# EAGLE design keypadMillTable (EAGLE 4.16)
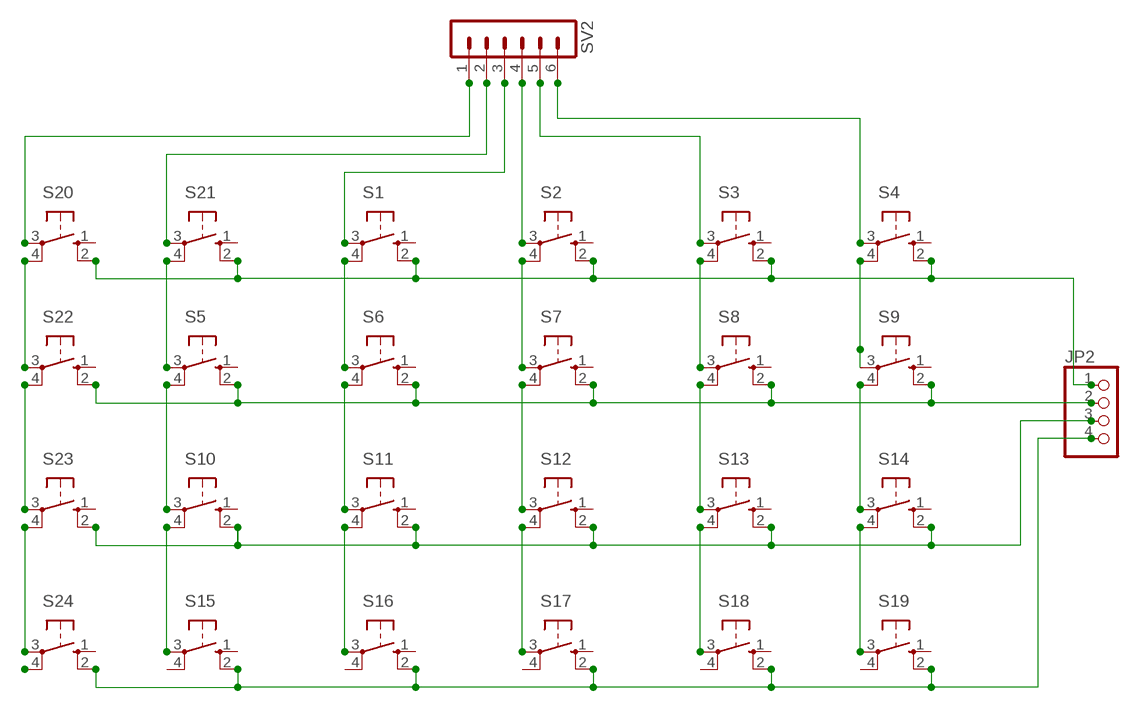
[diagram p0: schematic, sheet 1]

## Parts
JP2  PINHD-1X4  [1X04]
S1  10-XX  [B3F-10XX]
S2  10-XX  [B3F-10XX]
S3  10-XX  [B3F-10XX]
S4  10-XX  [B3F-10XX]
S5  10-XX  [B3F-10XX]
S6  10-XX  [B3F-10XX]
S7  10-XX  [B3F-10XX]
S8  10-XX  [B3F-10XX]
S9  10-XX  [B3F-10XX]
S10  10-XX  [B3F-10XX]
S11  10-XX  [B3F-10XX]
S12  10-XX  [B3F-10XX]
S13  10-XX  [B3F-10XX]
S14  10-XX  [B3F-10XX]
S15  10-XX  [B3F-10XX]
S16  10-XX  [B3F-10XX]
S17  10-XX  [B3F-10XX]
S18  10-XX  [B3F-10XX]
S19  10-XX  [B3F-10XX]
S20  10-XX  [B3F-10XX]
S21  10-XX  [B3F-10XX]
S22  10-XX  [B3F-10XX]
S23  10-XX  [B3F-10XX]
S24  10-XX  [B3F-10XX]
SV2  MA06-1  [MA06-1]

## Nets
N$1: S21.3(P) SV2.2
N$2: S10.4(P1) S15.3(P)
N$3: S4.3(P) SV2.6
N$4: S5.3(P) S21.4(P1)
N$5: S5.4(P1) S10.3(P)
N$7: S1.3(P) SV2.3
N$8: S1.4(P1) S6.3(P)
N$9: S6.4(P1) S11.3(P)
N$10: S2.3(P) SV2.4
N$11: S2.4(P1) S7.3(P)
N$12: S7.4(P1) S12.3(P)
N$13: S3.3(P) SV2.5
N$14: S3.4(P1) S8.3(P)
N$15: S8.4(P1) S13.3(P)
N$16: S14.4(P1) S19.3(P)
N$17: S9.4(P1) S14.3(P)
N$18: S4.4(P1) S9.3(P)
N$21: S11.4(P1) S16.3(P)
N$26: JP2.4 S15.2(S1) S16.2(S1) S17.2(S1) S18.2(S1) S19.2(S1) S24.2(S1)
N$28: S20.4(P1) S22.3(P)
N$29: JP2.1 S1.2(S1) S2.2(S1) S3.2(S1) S4.2(S1) S20.2(S1) S21.2(S1)
N$30: S22.4(P1) S23.3(P)
N$32: S23.4(P1) S24.3(P)
N$34: S24.4(P1)
N$35: S20.3(P) SV2.1
N$37: S12.4(P1) S17.3(P)
N$40: JP2.2 S5.2(S1) S6.2(S1) S7.2(S1) S8.2(S1) S9.2(S1) S22.2(S1)
N$46: JP2.3 S10.2(S1) S11.2(S1) S12.2(S1) S13.2(S1) S14.2(S1) S23.2(S1)
N$60: S13.4(P1) S18.3(P)
Unconnected: S1.1(S) S2.1(S) S3.1(S) S4.1(S) S5.1(S) S6.1(S) S7.1(S) S8.1(S) S9.1(S) S10.1(S) S11.1(S) S12.1(S) S13.1(S) S14.1(S) S15.1(S) S15.4(P1) S16.1(S) S16.4(P1) S17.1(S) S17.4(P1) S18.1(S) S18.4(P1) S19.1(S) S19.4(P1) S20.1(S) S21.1(S) S22.1(S) S23.1(S) S24.1(S)

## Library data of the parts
JP2 = pinhead:PINHD-1X4: PIN HEADER
S1-S24 = switch-omron:10-XX: OMRON SWITCH
SV2 = con-lstb:MA06-1: PIN HEADER

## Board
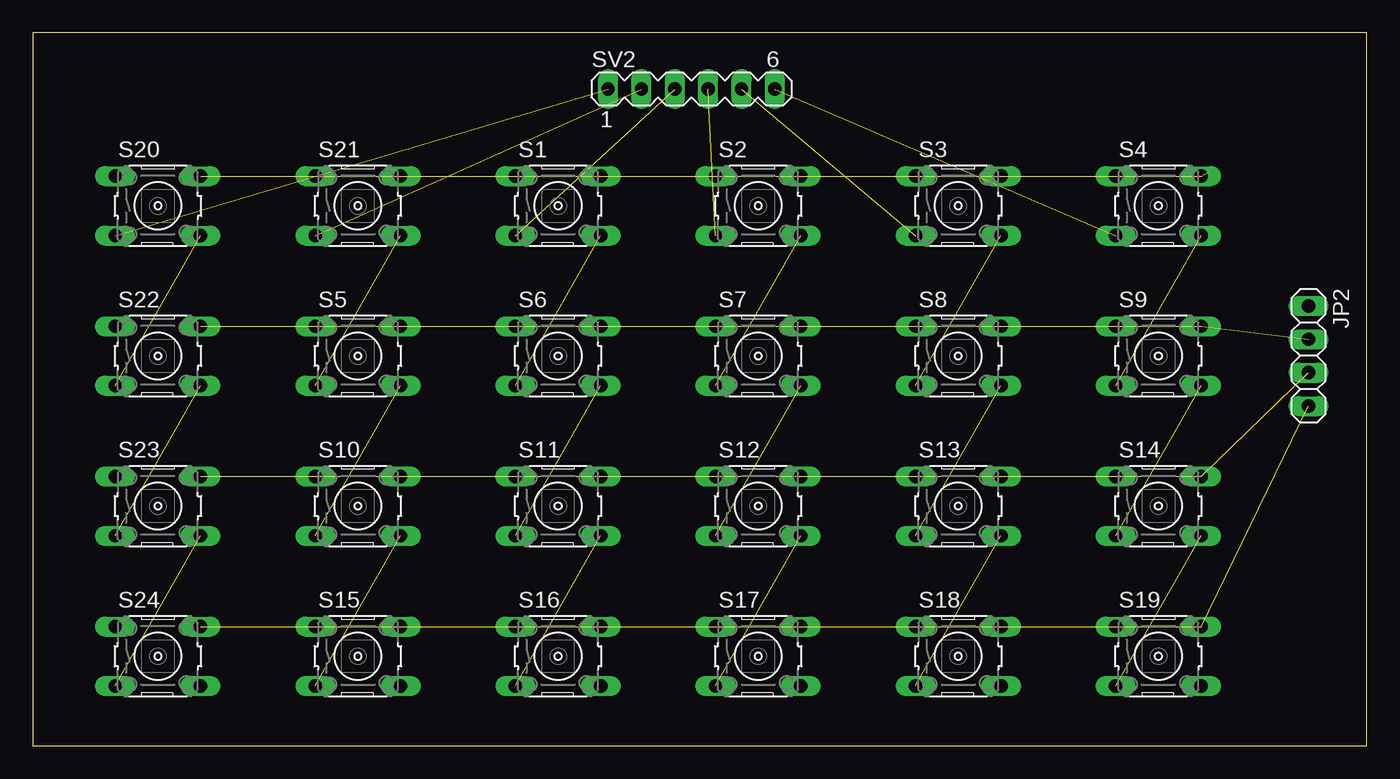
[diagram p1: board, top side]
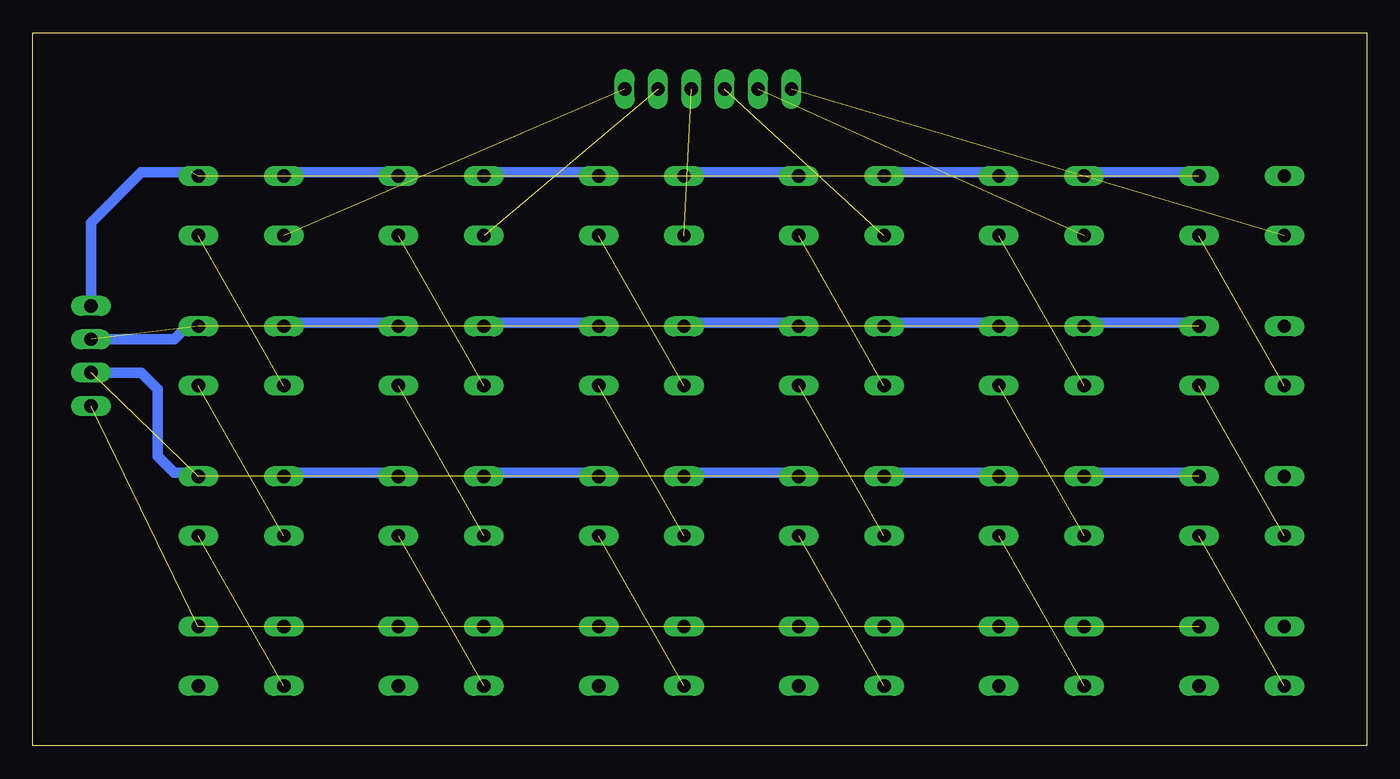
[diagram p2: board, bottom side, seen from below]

Size 101.58 x 54.28 mm. Coordinates in mm from the lower left corner, seen from the top.
Outline: 0,0 101.58,0 101.58,54.28 0,54.28 0,0
Copper layers (1*16): Top 0.035mm / dielectric 1.5mm / Bottom 0.035mm
Design rules "default": minimum track width 10mil, minimum drill 24mil, track to track 8mil, track to pad 8mil, pad to pad 8mil, via to via 8mil, smd to smd 8mil, copper to edge 40mil, drill to drill 8mil, minimum pad ring 10mil, minimum via ring 8mil, stop-mask expansion 4mil, vias tented up to drill 0mil, thermal gap 10mil

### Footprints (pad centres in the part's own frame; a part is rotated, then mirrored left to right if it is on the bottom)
1X04 = drill 1.016 long: 1 -3.81,0; 2 -1.27,0; 3 1.27,0; 4 3.81,0
B3F-10XX = drill 1.016 long: 1 -3.251,2.261; 2 3.251,2.261; 3 -3.251,-2.261; 4 3.251,-2.261
MA06-1 = drill 1.016 long: 1 -6.35,0; 2 -3.81,0; 3 -1.27,0; 4 1.27,0; 5 3.81,0; 6 6.35,0

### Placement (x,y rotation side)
JP2  97.15,29.68 270 top
S1  40,41.11 0 top
S2  55.24,41.11 0 top
S3  70.48,41.11 0 top
S4  85.72,41.11 0 top
S5  24.76,29.68 0 top
S6  40,29.68 0 top
S7  55.24,29.68 0 top
S8  70.48,29.68 0 top
S9  85.72,29.68 0 top
S10  24.76,18.25 0 top
S11  40,18.25 0 top
S12  55.24,18.25 0 top
S13  70.48,18.25 0 top
S14  85.72,18.25 0 top
S15  24.76,6.82 0 top
S16  40,6.82 0 top
S17  55.24,6.82 0 top
S18  70.48,6.82 0 top
S19  85.72,6.82 0 top
S20  9.52,41.11 0 top
S21  24.76,41.11 0 top
S22  9.52,29.68 0 top
S23  9.52,18.25 0 top
S24  9.52,6.82 0 top
SV2  50.16,50 0 top

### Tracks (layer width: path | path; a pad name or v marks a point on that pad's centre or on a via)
N$1  (1 unrouted)
N$2  (1 unrouted)
N$3  (1 unrouted)
N$4  (1 unrouted)
N$5  (1 unrouted)
N$7  (1 unrouted)
N$8  (1 unrouted)
N$9  (1 unrouted)
N$10  (1 unrouted)
N$11  (1 unrouted)
N$12  (1 unrouted)
N$13  (1 unrouted)
N$14  (1 unrouted)
N$15  (1 unrouted)
N$16  (1 unrouted)
N$17  (1 unrouted)
N$18  (1 unrouted)
N$19
  Bottom 0.813: 13.33,43.65 22.22,43.65
N$21  (1 unrouted)
N$22
  Bottom 0.813: 28.57,43.65 37.46,43.65
N$23
  Bottom 0.813: 43.81,43.65 51.43,43.65
N$24
  Bottom 0.813: 57.78,43.65 66.67,43.65
N$26  (6 unrouted)
N$27
  Bottom 0.813: 73.02,43.65 81.91,43.65
N$28  (1 unrouted)
N$29  (6 unrouted)
  Bottom 0.813: 89.53,43.65 93.34,43.65 97.15,39.84 JP2.1
N$30  (1 unrouted)
N$31
  Bottom 0.813: 13.33,32.22 20.95,32.22
N$32  (1 unrouted)
N$33
  Bottom 0.813: 28.57,32.22 36.19,32.22
N$35  (1 unrouted)
N$36
  Bottom 0.813: 43.81,32.22 52.7,32.22
N$37  (1 unrouted)
N$38
  Bottom 0.813: 59.05,32.22 67.94,32.22
N$39
  Bottom 0.813: 74.29,32.22 83.18,32.22
N$40  (6 unrouted)
  Bottom 0.813: 89.53,32.22 90.8,30.95 JP2.2
N$41
  Bottom 0.813: 13.33,20.79 22.22,20.79
N$42
  Bottom 0.813: 27.3,20.79 36.19,20.79
N$43
  Bottom 0.813: 43.81,20.79 51.43,20.79
N$44
  Bottom 0.813: 57.78,20.79 66.67,20.79
N$45
  Bottom 0.813: 74.29,20.79 81.91,20.79
N$46  (6 unrouted)
  Bottom 0.813: 88.26,20.79 90.8,20.79 92.07,22.06 92.07,27.14 93.34,28.41 JP2.3
N$60  (1 unrouted)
